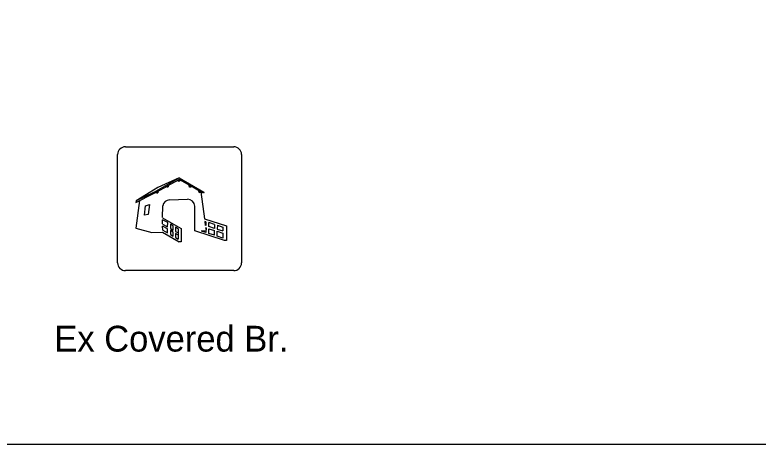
# Model space of a CAD drawing. Extents: x 42133 to 45533, y 41351 to 47951.
# Drawn here: x 43160.6 to 43376.5, y 46901.4 to 47026 of the extents above; entities that cross this region are included whole.
import ezdxf

# ---------------------------------------------------------------- set-up
doc = ezdxf.new("R2010")
doc.units = 0
doc.layers.add('P_ODOT_PLAN_Border', color=7, linetype='Continuous')
doc.layers.add('P_TRAF_SIGN_SignDetails', color=7, linetype='Continuous')

msp = doc.modelspace()

# ---------------------------------------------------------------- linework, layer by layer
at = {"layer": 'P_ODOT_PLAN_Border'}
msp.add_lwpolyline([(42208.34, 46901.35), (43808.34, 46901.35), (43808.34, 47901.35), (42208.34, 47901.35)], close=True, dxfattribs=at)
at = {"layer": 'P_TRAF_SIGN_SignDetails'}
for p, q in [((43192.74, 46987.72), (43224.22, 46987.72)), ((43190.49, 46953.99), (43190.49, 46985.48)), ((43226.47, 46985.48), (43226.47, 46953.99)), ((43200.89, 46974.42), (43208.38, 46978.71)), ((43208.38, 46978.71), (43202.18, 46975.9)), ((43205.15, 46976.47), (43208.16, 46978.15)), ((43208.16, 46977.87), (43207.69, 46977.73)), ((43208.54, 46977.87), (43207.96, 46977.66)), ((43208.16, 46978.24), (43208.54, 46978.23)), ((43208.16, 46978.24), (43208.16, 46977.87)), ((43208.16, 46977.87), (43208.54, 46977.87)), ((43208.38, 46978.71), (43215.49, 46974.51)), ((43208.54, 46978.23), (43208.54, 46977.87)), ((43211.5, 46976.46), (43208.55, 46978.13)), ((43202.18, 46975.9), (43195.89, 46971.99)), ((43202.05, 46974.74), (43204.84, 46976.29)), ((43204.84, 46976.1), (43204.42, 46976.02)), ((43205.21, 46976.1), (43204.73, 46975.98)), ((43204.84, 46976.48), (43205.21, 46976.46)), ((43204.84, 46976.48), (43204.84, 46976.11)), ((43204.84, 46976.11), (43205.21, 46976.1)), ((43205.21, 46976.46), (43205.21, 46976.1)), ((43211.49, 46976.46), (43211.06, 46976.39)), ((43211.49, 46976.09), (43211.14, 46976.05)), ((43211.87, 46976.08), (43211.36, 46975.96)), ((43211.49, 46976.46), (43211.87, 46976.44)), ((43211.49, 46976.46), (43211.49, 46976.09)), ((43211.49, 46976.09), (43211.87, 46976.08)), ((43211.87, 46976.44), (43211.87, 46976.08)), ((43214.31, 46974.87), (43211.87, 46976.25)), ((43195.82, 46971.55), (43200.9, 46974.1)), ((43200.89, 46974.42), (43195.89, 46971.99)), ((43200.9, 46974.1), (43200.89, 46974.42)), ((43200.9, 46974.1), (43201.77, 46974.58)), ((43201.76, 46974.75), (43202.14, 46974.73)), ((43201.76, 46974.75), (43201.76, 46974.37)), ((43201.76, 46974.37), (43202.14, 46974.36)), ((43202.14, 46974.73), (43202.14, 46974.36)), ((43214.31, 46974.87), (43213.89, 46974.79)), ((43214.31, 46974.49), (43213.97, 46974.45)), ((43214.69, 46974.47), (43214.2, 46974.37)), ((43214.31, 46974.87), (43214.69, 46974.84)), ((43214.31, 46974.87), (43214.31, 46974.49)), ((43214.31, 46974.49), (43214.69, 46974.47)), ((43214.69, 46974.84), (43214.69, 46974.47)), ((43215.45, 46974.21), (43214.69, 46974.65)), ((43214.69, 46974.61), (43215.69, 46966.75)), ((43215.49, 46974.51), (43215.45, 46974.21)), ((43196.86, 46972.07), (43195.8, 46964.03)), ((43195.89, 46971.99), (43195.82, 46971.55)), ((43205.58, 46972.26), (43210.76, 46972.46)), ((43198.25, 46967.86), (43198.59, 46970.56)), ((43198.59, 46970.56), (43199.74, 46971)), ((43199.74, 46971), (43199.37, 46968.07)), ((43203.57, 46967.13), (43203.62, 46970.58)), ((43212.92, 46963.27), (43212.91, 46970.46)), ((43199.37, 46968.07), (43198.25, 46967.86)), ((43203.57, 46967.11), (43208.96, 46963.96)), ((43212.9, 46967.43), (43212.9, 46967.43)), ((43215.69, 46966.75), (43222.07, 46964.78)), ((43203.56, 46965.29), (43203.55, 46966.54)), ((43205.03, 46965.69), (43203.55, 46966.54)), ((43203.62, 46963.5), (43203.56, 46964.69)), ((43205.02, 46963.86), (43203.56, 46964.69)), ((43203.57, 46965.27), (43204.97, 46964.44)), ((43204.97, 46964.44), (43205.03, 46965.69)), ((43205.85, 46965.22), (43205.8, 46963.97)), ((43206.64, 46964.76), (43205.85, 46965.22)), ((43206.62, 46963.5), (43206.64, 46964.76)), ((43216.12, 46965.95), (43215.8, 46966.05)), ((43215.8, 46966.04), (43215.95, 46964.94)), ((43216.1, 46964.89), (43215.96, 46964.93)), ((43216.12, 46965.95), (43216.1, 46964.89)), ((43217, 46964.55), (43216.97, 46965.69)), ((43218.64, 46965.16), (43216.97, 46965.69)), ((43218.64, 46965.16), (43218.67, 46964.02)), ((43219.46, 46964.91), (43219.43, 46963.78)), ((43219.46, 46964.91), (43221.07, 46964.41)), ((43222.07, 46964.78), (43222.07, 46960.54)), ((43195.8, 46964.03), (43200.39, 46962.79)), ((43200.39, 46962.79), (43203.49, 46962.91)), ((43203.49, 46962.91), (43208.34, 46960.12)), ((43203.62, 46963.5), (43205, 46962.68)), ((43205, 46962.68), (43205.02, 46963.86)), ((43205.8, 46963.97), (43206.62, 46963.5)), ((43205.82, 46963.41), (43205.83, 46962.2)), ((43206.66, 46962.93), (43205.82, 46963.41)), ((43206.62, 46961.72), (43206.66, 46962.93)), ((43207.28, 46964.4), (43207.28, 46963.1)), ((43208.11, 46963.93), (43207.28, 46964.4)), ((43207.28, 46963.1), (43208.13, 46962.68)), ((43207.28, 46962.57), (43207.28, 46961.35)), ((43208.14, 46962.09), (43207.28, 46962.57)), ((43208.11, 46963.93), (43208.11, 46960.88)), ((43208.96, 46963.96), (43208.96, 46960.12)), ((43221.49, 46960.54), (43212.92, 46963.27)), ((43216.15, 46963.32), (43214.78, 46963.24)), ((43216.15, 46962.84), (43214.81, 46963.24)), ((43216.04, 46964.23), (43216.16, 46964.19)), ((43216.04, 46964.23), (43216.16, 46963.6)), ((43216.16, 46964.19), (43216.15, 46962.84)), ((43218.67, 46964.02), (43217, 46964.55)), ((43217, 46962.56), (43217.03, 46963.93)), ((43218.63, 46962.03), (43217, 46962.56)), ((43217.03, 46963.93), (43218.63, 46963.42)), ((43218.63, 46962.03), (43218.63, 46963.42)), ((43219.36, 46961.79), (43219.38, 46963.16)), ((43219.38, 46963.16), (43221.07, 46962.61)), ((43219.43, 46963.78), (43221.07, 46963.27)), ((43221.07, 46964.41), (43221.07, 46963.27)), ((43221.07, 46962.61), (43221.07, 46961.2)), ((43205.83, 46962.2), (43206.62, 46961.72)), ((43207.28, 46961.35), (43208.11, 46960.88)), ((43221.07, 46961.2), (43219.36, 46961.79)), ((43222.07, 46960.54), (43221.49, 46960.54)), ((43208.96, 46960.12), (43208.34, 46960.12)), ((43224.22, 46951.74), (43192.74, 46951.74))]:
    msp.add_line(p, q, dxfattribs=at)
for centre, radius, start, end in [((43192.74, 46985.48), 2.25, 90, 180), ((43224.22, 46985.48), 2.25, 0, 90), ((43205.58, 46970.28), 1.99, 90.0628, 171.3645), ((43210.82, 46970.37), 2.09, 2.5563, 91.6173), ((43192.74, 46953.99), 2.25, 180, 270), ((43224.22, 46953.99), 2.25, 270, 0)]:
    msp.add_arc(centre, radius, start, end, dxfattribs=at)

# ---------------------------------------------------------------- texts
msp.add_text('Ex Covered Br.', height=7.5, dxfattribs=at).set_placement((43172.1, 46928.23))

doc.saveas('drawing.dxf')
